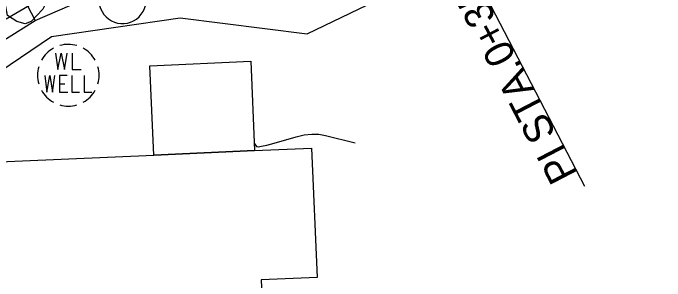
# Model space of a CAD drawing. Extents: x 2030588 to 2035216, y 462285 to 465007.
# Drawn here: x 2031319.5 to 2031382.9, y 464317.2 to 464343.2 of the extents above; entities that cross this region are included whole.
import ezdxf

# ---------------------------------------------------------------- set-up
doc = ezdxf.new("R2010")
doc.units = 0
for name, color, linetype in [('BD_X_Building', 7, 'Continuous'), ('BD_X_Porch_or_Deck', 7, 'Continuous'), ('DR_X_Culvert', 7, 'Continuous'), ('DT_P_Slope_Break_Line', 7, 'Continuous'), ('DT_X_Contour_Minor', 7, 'Continuous'), ('GE_P_Alignment_100_Cardinal_Points', 7, 'Continuous'), ('HY_X_Water_Well', 7, 'Continuous'), ('MD_P_CONST_LIMITS', 7, 'Continuous'), ('SV_X_Break_Lines', 7, 'Continuous'), ('VG_X_Cells', 7, 'Continuous')]:
    doc.layers.add(name, color=color, linetype=linetype)

msp = doc.modelspace()

# ---------------------------------------------------------------- linework, layer by layer
at = {"layer": 'BD_X_Building'}
msp.add_lwpolyline([(2031312.882, 464304.375), (2031312.354, 464316.266), (2031311.814, 464328.452), (2031319.655, 464328.798), (2031324.902, 464329.03), (2031333.154, 464329.394), (2031342.968, 464329.827), (2031348.498, 464330.072), (2031349.056, 464317.507), (2031343.615, 464317.267), (2031344.126, 464305.755), (2031336.745, 464305.429), (2031327.934, 464305.04), (2031320.082, 464304.693)], close=True, dxfattribs=at)
at = {"layer": 'BD_X_Porch_or_Deck'}
msp.add_lwpolyline([(2031333.154, 464329.394), (2031332.769, 464338.073), (2031342.583, 464338.506), (2031342.968, 464329.827)], close=True, dxfattribs=at)
at = {"layer": 'DR_X_Culvert'}
msp.add_line((2031343.516, 464357.134), (2031318.806, 464342.593), dxfattribs=at)
at = {"layer": 'DT_P_Slope_Break_Line'}
for p, q in [((2031318.809, 464347.881), (2031321.623, 464342.459)), ((2031321.623, 464342.459), (2031326.205, 464344.485)), ((2031317.366, 464339.809), (2031321.623, 464342.459))]:
    msp.add_line(p, q, dxfattribs=at)
at = {"layer": 'DT_X_Contour_Minor'}
msp.add_lwpolyline([(2031342.936, 464330.555), (2031343.156, 464330.237), (2031343.298, 464330.205), (2031343.629, 464330.248), (2031344.149, 464330.364), (2031344.857, 464330.555), (2031346.999, 464331.161), (2031347.78, 464331.341), (2031348.514, 464331.425), (2031349.201, 464331.413), (2031349.843, 464331.307), (2031352.728, 464330.585)], dxfattribs=at)
at = {"layer": 'GE_P_Alignment_100_Cardinal_Points'}
msp.add_line((2031354.307, 464366.308), (2031375.038, 464326.372), dxfattribs=at)
at = {"layer": 'HY_X_Water_Well'}
for p, q in [((2031324.852, 464337.146), (2031324.852, 464337.146)), ((2031323.983, 464336.323), (2031324.523, 464336.323))]:
    msp.add_line(p, q, dxfattribs=at)
for points in [[(2031323.605, 464339.305), (2031323.844, 464337.706), (2031324.159, 464339.305), (2031324.474, 464337.706), (2031324.726, 464339.305)], [(2031325.23, 464339.305), (2031325.23, 464337.706), (2031326.099, 464337.706)], [(2031322.561, 464337.116), (2031322.771, 464335.516), (2031323.046, 464337.116), (2031323.322, 464335.516), (2031323.542, 464337.116)], [(2031324.744, 464337.116), (2031323.983, 464337.116), (2031323.983, 464335.516), (2031324.799, 464335.516)], [(2031325.184, 464337.116), (2031325.184, 464335.516), (2031325.945, 464335.516)], [(2031326.386, 464337.116), (2031326.386, 464335.516), (2031327.146, 464335.516)]]:
    msp.add_lwpolyline(points, dxfattribs=at)
for major_axis, start_param, end_param in [((-2.009, 2.228), 5.269118, 5.827548), ((-2.006, 2.23), 6.056487, 6.614489), ((-2.008, 2.228), 4.484831, 5.042833), ((-2.018, 2.22), 0.553764, 1.113263), ((-1.988, 2.246), 3.708628, 4.26706), ((-2.01, 2.226), 1.342195, 1.900198), ((-2.004, 2.232), 2.915787, 3.474762), ((-2.005, 2.231), 2.129118, 2.687548)]:
    msp.add_ellipse((2031324.85, 464337.146), major_axis=major_axis, ratio=0.999987, start_param=start_param, end_param=end_param, dxfattribs=at)
at = {"layer": 'MD_P_CONST_LIMITS'}
for points in [[(2031335.72, 464342.732), (2031348.065, 464341.156), (2031359.796, 464346.821), (2031370.029, 464354.448), (2031376.828, 464361.456), (2031382.871, 464378.84), (2031377.102, 464386.742), (2031358.079, 464381.314), (2031336.103, 464372.313), (2031297.636, 464355.997), (2031288.946, 464369.084), (2031270.232, 464370.675), (2031259.85, 464435.069), (2031243.038, 464457.678), (2031227.121, 464556.394)], [(2031299.488, 464314.858), (2031300.288, 464323.242), (2031312.015, 464333.369), (2031323.227, 464340.901), (2031335.72, 464342.732)]]:
    msp.add_lwpolyline(points, dxfattribs=at)
at = {"layer": 'SV_X_Break_Lines'}
msp.add_lwpolyline([(2031322.385, 464343.559), (2031321.244, 464342.355), (2031320.663, 464342.157), (2031319.834, 464342.369), (2031318.925, 464342.941), (2031318.661, 464344.333), (2031318.871, 464346.105), (2031319.086, 464347.098), (2031319.773, 464346.725), (2031321.658, 464346.402), (2031323.025, 464345.787), (2031322.825, 464344.515)], close=True, dxfattribs=at)
at = {"layer": 'VG_X_Cells'}
msp.add_ellipse((2031330.119, 464344.446), major_axis=(1.525, -1.7), ratio=0.999987, start_param=4.067612, end_param=7.462445, dxfattribs=at)

# ---------------------------------------------------------------- texts
at = {"layer": 'GE_P_Alignment_100_Cardinal_Points'}
for s, p in [('0+35.00', (2031368.466, 464338.94)), (' STA. ', (2031372.82, 464330.552)), ('PI', (2031374.383, 464327.542))]:
    msp.add_text(s, height=2.7997, rotation=117.43362, dxfattribs=at).set_placement(p)

doc.saveas('drawing.dxf')
